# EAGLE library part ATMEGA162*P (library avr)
MIKROCONTROLLER ATmega162 16kB Flash 2kB RAM 2 USARTS ATmega162 = 2,7-5,5V or ATmega162V = 1,8-5,5V
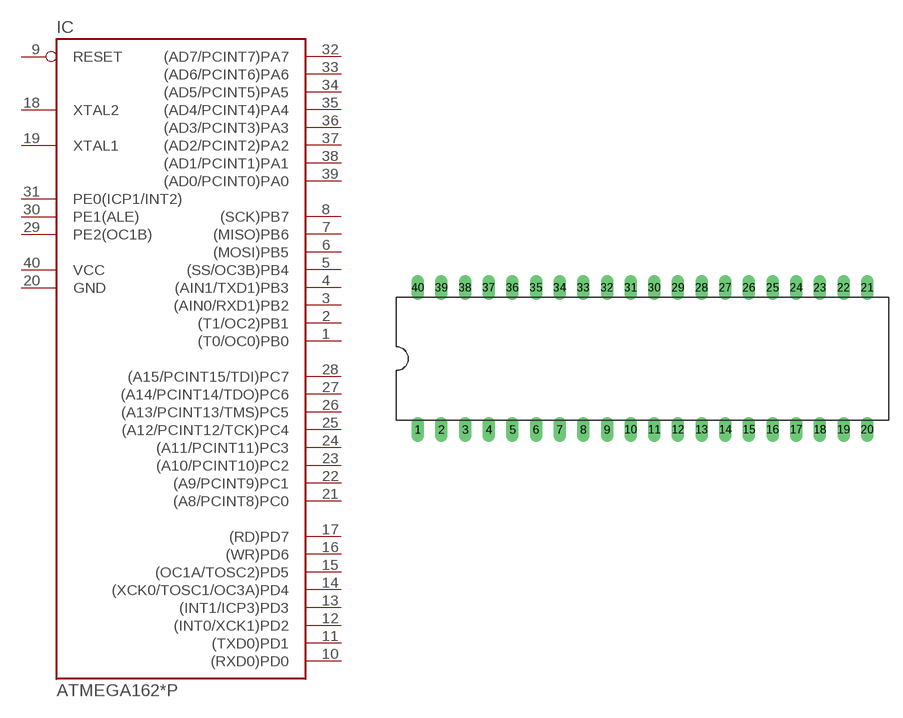
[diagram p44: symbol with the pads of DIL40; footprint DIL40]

Designator prefix IC

## ATMEGA162-16P, ATMEGA162V-8P  [DIL40]
1  (T0/OC0)PB0
2  (T1/OC2)PB1
3  (AIN0/RXD1)PB2
4  (AIN1/TXD1)PB3
5  (SS/OC3B)PB4
6  (MOSI)PB5
7  (MISO)PB6
8  (SCK)PB7
9  RESET  in
10  (RXD0)PD0
11  (TXD0)PD1
12  (INT0/XCK1)PD2
13  (INT1/ICP3)PD3
14  (XCK0/TOSC1/OC3A)PD4
15  (OC1A/TOSC2)PD5
16  (WR)PD6
17  (RD)PD7
18  XTAL2
19  XTAL1
20  GND  pwr
21  (A8/PCINT8)PC0
22  (A9/PCINT9)PC1
23  (A10/PCINT10)PC2
24  (A11/PCINT11)PC3
25  (A12/PCINT12/TCK)PC4
26  (A13/PCINT13/TMS)PC5
27  (A14/PCINT14/TDO)PC6
28  (A15/PCINT15/TDI)PC7
29  PE2(OC1B)
30  PE1(ALE)
31  PE0(ICP1/INT2)
32  (AD7/PCINT7)PA7
33  (AD6/PCINT6)PA6
34  (AD5/PCINT5)PA5
35  (AD4/PCINT4)PA4
36  (AD3/PCINT3)PA3
37  (AD2/PCINT2)PA2
38  (AD1/PCINT1)PA1
39  (AD0/PCINT0)PA0
40  VCC  pwr

## Footprint DIL40 (pad centres in mm)
Dual In Line
drill 0.813 long: 1 -24.13,-7.62; 2 -21.59,-7.62; 3 -19.05,-7.62; 4 -16.51,-7.62; 5 -13.97,-7.62; 6 -11.43,-7.62; 7 -8.89,-7.62; 8 -6.35,-7.62; 9 -3.81,-7.62; 10 -1.27,-7.62; 11 1.27,-7.62; 12 3.81,-7.62; 13 6.35,-7.62; 14 8.89,-7.62; 15 11.43,-7.62; 16 13.97,-7.62; 17 16.51,-7.62; 18 19.05,-7.62; 19 21.59,-7.62; 20 24.13,-7.62; 21 24.13,7.62; 22 21.59,7.62; 23 19.05,7.62; 24 16.51,7.62; 25 13.97,7.62; 26 11.43,7.62; 27 8.89,7.62; 28 6.35,7.62; 29 3.81,7.62; 30 1.27,7.62; 31 -1.27,7.62; 32 -3.81,7.62; 33 -6.35,7.62; 34 -8.89,7.62; 35 -11.43,7.62; 36 -13.97,7.62; 37 -16.51,7.62; 38 -19.05,7.62; 39 -21.59,7.62; 40 -24.13,7.62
